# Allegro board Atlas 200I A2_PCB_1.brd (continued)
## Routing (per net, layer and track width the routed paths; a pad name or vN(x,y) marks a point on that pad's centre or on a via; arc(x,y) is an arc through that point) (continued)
TYPEC_CC2: length 12.5
  TOP w0.203: U6.4 v1(102.07,12.01)
  ART03 w0.203: v1(102.07,12.01) 102.18,11.9 102.18,10.08 101.61,9.51 101.61,7.9 103.16,6.34 106.53,6.34 106.92,5.96 106.92,5.35 J4.17
UART0_RX: length 52.3
  TOP w0.203: R253.1 124.92,32.64 125.12,32.44 v1(125.37,32.44) ; R704.2 94.11,46.1 v1(94.44,46.43) 94.25,46.62 J16.14
  ART03 w0.203: v1(125.37,32.44) 125.98,33.05 125.98,35.56 126.88,36.46 126.88,43.51 125.11,45.28 115.85,45.28 114.36,43.78 113.56,43.78 112.59,44.75 110.38,44.75 109.51,43.89 106.03,43.89 105.57,43.43 100.94,43.43 97.94,46.43 v1(94.44,46.43)
UART0_RX_R: length 102.1
  TOP w0.203: v1(121.54,105.79) 121.92,105.79 122.17,105.54 R113.1 ; v1(128.27,36.96) 127.29,36.96 126.5,37.75 U30.3 ; v1(122.57,70.1) 123.12,70.1 R433.1
  ART03 w0.203: v1(122.57,70.1) 119.57,70.1 118.16,68.69 118.16,67.88 114.34,64.06 113.96,64.06 113.69,64.33 113.69,64.71 111.43,66.97 111.43,68.36 111.91,68.84 111.91,77.73 110.74,78.9 110.74,87.44 113.72,90.41 113.72,96.43 120.21,102.92 120.48,102.92 121.54,103.98 v1(121.54,105.79)
  ART04 w0.203: v1(128.27,36.96) 128.98,37.67 128.98,38.93 129.42,39.36 129.42,49.12 124.56,53.97 124.56,69.19 123.75,70 122.66,70 v1(122.57,70.1)
UART0_TX: length 54.4
  TOP w0.203: v1(125.37,31.42) 125.86,31.91 125.86,33.17 R252.1 ; J16.16 93.75,47.55 v1(93.07,46.87) 93.09,46.85 R703.2
  ART03 w0.203: v1(93.07,46.87) 93.97,45.97 97.71,45.97 100.66,43.03 105.74,43.03 106.2,43.48 112.48,43.48 112.98,42.99 117.11,42.99 118.12,44 125.58,44 126.47,43.11 126.47,41.31 125.53,40.36 125.53,33.45 124.84,32.77 124.84,31.94 v1(125.37,31.42)
UART0_TX_R: length 36.3
  TOP w0.203: v1(128.27,37.72) 127.81,37.72 127.69,37.59 127.3,37.59 127.15,37.75 U30.2 ; R51.1 R36.1 123.14,67.06 v1(123.07,67.06)
  ART04 w0.203: v1(128.27,37.72) 127.97,38.02 127.97,40.91 128.92,41.87 128.92,48.9 124.08,53.75 124.08,66.05 v1(123.07,67.06)
UART2_CTX: length 71.6
  TOP w0.203: J16.143 62,59.03 62.89,59.92 62.89,67.15 69.27,73.53 78.37,73.53 80.2,71.7 82.06,71.7 82.8,72.44 v1(82.8,72.64) ; R7.1 v1(115.31,68.23)
  ART04 w0.203: v1(115.31,68.23) 114.43,69.11 109.63,69.11 108.33,70.41 102.11,70.41 101.53,70.99 97.7,70.99 95.91,69.2 92.41,69.2 92.23,69.03 91.85,69.03 91.72,69.15 88.61,69.15 88.09,69.67 86.77,69.67 84.98,71.47 83.98,71.47 v1(82.8,72.64)
UART2_CTX_R: length 5.5
  TOP w0.203: R21.2 113.37,75.31 114.35,76.29 U33.11
UART2_RTX: length 73.7
  TOP w0.203: J16.145 61.5,59.39 62.26,60.14 62.26,67.09 69.1,73.94 78.54,73.94 80.37,72.1 81.89,72.1 82.25,72.45 82.25,72.75 82.77,73.27 83.06,73.27 v1(83.69,72.64) ; R19.1 v1(116.42,68.23)
  ART04 w0.203: v1(116.42,68.23) 115.13,69.52 109.79,69.52 108.5,70.82 102.28,70.82 101.7,71.4 97.13,71.4 95.99,72.54 90.5,72.54 90.3,72.34 90.3,71.75 89.66,71.12 85.9,71.12 85.14,71.88 84.46,71.88 v1(83.69,72.64)
UART2_RTX_R: length 6.7
  TOP w0.203: R29.1 111.07,74.3 111.42,74.65 113.54,74.65 115,76.1 U33.10
UART3_CTX: length 166.4
  TOP w0.203: R50.1 R46.2 ; v1(92.15,50.65) 92.25,50.54 J16.22
  TOP w0.381: R50.1 v1(5.28,106.07)
  ART03 w0.203: v1(5.28,106.07) 5.99,105.36 14.16,105.36 16.24,103.28 20.92,103.28 21.28,103.63 26.67,103.63 29.37,100.93 44.81,100.93 48.54,97.19 53.13,97.19 55.05,95.28 60.48,95.28 v1(60.93,95.73) ; v1(103.89,87.33) 103.89,87.08 103.43,86.63 103.43,86.33 100.3,83.21 100.3,76.49 99.29,75.47 99.29,70.46 98.55,69.73 98.55,67.68 97.28,66.41 97.28,65.2 95.97,63.89 95.97,62.2 92.96,59.19 91.83,59.19 90.64,57.99 90.64,53.64 91.49,52.79 91.49,51.3 v1(92.15,50.65)
  BOTTOM w0.203: v1(103.89,87.33) 104.62,88.05 104.62,89.49 102.39,91.72 101,91.72 96.75,95.97 96.75,96.51 96.48,96.77 96.1,96.77 94.11,98.77 94.11,101.18 89.51,105.78 85.01,105.78 84.72,105.49 84.06,105.49 82.66,104.09 80.99,104.09 77.74,100.84 66.04,100.84 v1(60.93,95.73)
UART3_RTX: length 168.3
  TOP w0.203: v1(92.15,51.92) 92.15,51.29 91.69,50.84 91.69,50.46 91.75,50.4 J16.24 ; R69.2 R67.1 6.91,105.92 v1(7.06,106.07)
  ART03 w0.203: v1(103.89,86.44) 103.89,86.22 100.71,83.04 100.71,76.32 100.43,76.04 100.43,71.03 98.96,69.56 98.96,67.51 98.17,66.72 98.17,63.47 93.32,58.62 91.83,58.62 91.04,57.83 91.04,53.81 92.15,52.71 v1(92.15,51.92) ; v1(58.9,95.73) 55.17,95.73 53.3,97.6 48.71,97.6 44.98,101.33 29.54,101.33 26.28,104.6 21.67,104.6 20.75,103.68 18.23,103.68 15.38,106.53 7.52,106.53 v1(7.06,106.07)
  BOTTOM w0.203: v1(58.9,95.73) 64.55,101.38 76.75,101.38 80.7,105.33 83.33,105.33 83.89,105.89 84.47,105.89 85.33,106.76 89.37,106.76 93.03,103.1 93.58,103.1 94.51,102.16 94.51,98.93 96.27,97.18 96.65,97.18 97.16,96.68 97.16,96.14 101.17,92.13 103.03,92.13 105.71,89.45 105.71,87.81 104.34,86.44 v1(103.89,86.44)
UART3_RX: length 172.8
  TOP w0.203: v1(1.63,106.05) R49.1 R47.2 ; J16.26 91.25,50.92 90.88,51.29 v1(90.88,51.92)
  ART03 w0.203: v1(60.93,94.46) 60.48,94.01 58.65,94.01 58.27,94.39 54.79,94.39 52.89,96.29 48.3,96.29 44.47,100.12 29.04,100.12 26.33,102.82 21.61,102.82 21.26,102.46 10.73,102.46 8.79,104.41 3.26,104.41 v1(1.63,106.05) ; v1(103.89,88.29) 103.15,87.56 103.15,87.09 102.48,86.42 102.48,85.96 98.4,81.88 98.4,76.66 97.02,75.28 97.02,75 98.12,73.89 98.12,67.82 96.88,66.58 96.88,65.37 95.56,64.06 95.56,62.37 92.95,59.75 91.47,59.75 89.54,57.83 89.54,54.35 90.23,53.66 90.23,53.48 90.88,52.83 v1(90.88,51.92)
  BOTTOM w0.203: v1(60.93,94.46) 66.9,100.43 77.9,100.43 81.16,103.68 82.83,103.68 84.22,105.08 85.04,105.08 85.33,105.37 89.01,105.37 93,101.38 93,99.81 93.4,99.41 93.4,96.15 94.05,95.5 96.53,95.5 100.72,91.31 102.22,91.31 104.21,89.32 104.21,88.61 v1(103.89,88.29)
UART3_TX: length 170.7
  TOP w0.203: v1(90.32,51.06) 90.75,50.63 J16.28 ; R68.2 R66.1 v1(3.3,106.05)
  ART03 w0.203: v1(90.32,51.06) 90.32,52.81 89.82,53.31 89.82,53.49 89.14,54.18 89.14,57.99 91.32,60.18 92.8,60.18 95.16,62.53 95.16,64.22 96.47,65.54 96.47,66.74 97.72,67.99 97.72,73.55 96.4,74.86 96.4,75.36 97.99,76.95 97.99,82.05 102.07,86.13 102.07,86.59 102.75,87.26 102.75,87.91 103.63,88.8 v1(103.63,89.26) ; v1(3.3,106.05) 4.39,104.95 13.99,104.95 16.07,102.87 21.09,102.87 21.45,103.23 26.5,103.23 29.2,100.52 44.64,100.52 48.46,96.7 53.05,96.7 54.96,94.79 58.57,94.79 v1(58.9,94.46)
  BOTTOM w0.203: v1(58.9,94.46) 59.36,94.01 61.12,94.01 66.99,99.87 78.2,99.87 81.51,103.17 82.89,103.17 84.39,104.67 85.21,104.67 85.49,104.96 88.84,104.96 92.59,101.22 92.59,99.64 92.99,99.24 92.99,95.11 93.86,94.23 97.22,94.23 100.55,90.91 101.98,90.91 v1(103.63,89.26)
UHT_ALARM: length 59.9
  TOP w0.203: v1(96.04,51.26) 96.27,51.49 97.24,51.49 98.07,52.31 98.07,52.62 99.25,53.8 100.03,53.8 100.76,54.53 v1(101.22,54.53) ; R54.1 92.55,14.13 92.34,13.92 92.34,12.59 92.49,12.44 v1(92.49,11.98)
  TOP w0.254: J16.303 v1(102.5,57.64)
  ART03 w0.203: v1(92.49,11.98) 93.2,11.98 95.83,14.61 95.83,19.34 93.88,21.3 93.88,31.14 94.61,31.88 v1(95.25,31.88)
  ART04 w0.203: v1(95.25,31.88) 95.3,31.88 99.01,35.59 99.01,36.58 98.73,36.86 98.73,44.12 96.85,46 96.85,49.91 96.04,50.73 v1(96.04,51.26)
  BOTTOM w0.203: v1(102.5,57.64) 102.5,55.81 v1(101.22,54.53)
UPDATE_MODE: length 104.1
  TOP w0.203: J16.139 63,58.45 67.29,62.74 80.7,62.74 85.6,67.64 98.6,67.64 100.69,69.72 v1(100.79,69.72) ; v1(126.38,31.42) 126.67,31.42 127.07,31.82 R461.1
  ART04 w0.203: v1(126.38,31.42) 128.75,33.79 128.75,35.81 127.56,37.01 127.56,41.14 128.3,41.87 128.3,48.71 125.01,52 123.31,52 122.43,52.89 122.43,57.44 120.43,59.44 117.26,59.44 115.93,60.77 115.93,61.09 107.82,69.19 101.32,69.19 v1(100.79,69.72)
UPDATE_MODE_R: length 10.6
  TOP w0.203: R461.2 127.88,32.04 128.13,31.79 130.12,31.79 130.33,32 R462.1 C285.2 131.49,32.01 132.03,31.47 S1.2 S1.1
USB0_5V0: length 9
  TOP w0.254: D2.1 57.79,25.02 v1(58.04,25.27)
  BOTTOM w0.254: v1(58.04,25.27) 56.71,25.27 55.64,24.2 55.64,22.79 54.03,21.18 52.78,21.18
  vias: v1(45.06,28.98) v1(50.08,10.97) v1(50.08,10.21) v1(50.08,9.45) v1(50.08,8.69) v1(50.08,7.92) v1(50.08,7.16)
USB1_5V0: length 9.8
  TOP w0.254: v1(55.75,22.1) 56.65,22.99 D2.2
  BOTTOM w0.254: v1(50.16,17.09) 51.84,17.09 53.89,19.15 53.89,20.24 v1(55.75,22.1)
  vias: v1(49.66,17.09) v1(49.66,16.59) v1(50.16,16.59)
USB2_1_CONN_DN: length 21.1
  TOP w0.188: U31.1 47.91,26.69 47.67,26.93 47.67,27.19 47.86,27.38 48.03,27.38 48.13,27.28 48.13,27.13 48.24,27.03 48.51,27.03 48.56,27.08 48.56,27.25 48.69,27.38 48.99,27.38 49.18,27.19 v1(49.18,26.63) 49.45,26.37 T5.3 50.6,26.37 R260.2
  BOTTOM w0.188: v1(49.18,26.63) 48.91,26.36 45.95,26.36 41.73,22.15 41.73,20.88 41.37,20.52 41.13,20.52 40.84,20.4 40.58,20.14 39.55,20.14 38.95,19.54 J5.2
USB2_1_CONN_DP: length 21.4
  TOP w0.188: R261.2 50.6,25.55 T5.2 49.34,25.55 v1(49.18,25.71) 48.74,25.53 48.53,25.32 48.41,25.27 46.47,25.27 46.01,25.72 U31.3
  BOTTOM w0.188: v1(49.18,25.71) 49.18,25.75 48.95,25.98 47.77,25.98 47.58,25.79 47.58,25.74 47.39,25.55 47.01,25.55 46.83,25.74 46.83,25.79 46.64,25.98 46.1,25.98 44.94,24.82 44.94,24.55 45.13,24.36 45.13,24.1 44.86,23.83 44.6,23.83 44.41,24.02 44.14,24.02 43.87,23.75 43.87,23.49 44.06,23.3 44.06,23.03 43.8,22.77 43.53,22.77 43.34,22.95 43.08,22.95 42.11,21.99 42.11,20.73 41.53,20.14 41.21,20.14 41.06,20.08 40.83,19.85 40.83,17.93 40.95,17.81 J5.3
USB2_1_DN: length 82.8
  TOP w0.188: T21.1 103.71,15.65 v1(103.77,15.71) ; J16.123 67,55.08 66.94,55.02 66.94,52.9 68.25,51.59 69.28,51.59 69.63,51.94 70.03,51.94 70.38,51.59 70.78,51.59 71.14,51.94 71.53,51.94 71.89,51.59 72.28,51.59 72.41,51.71 73.27,51.71 73.39,51.59 75.02,51.59 v1(75.25,51.82)
  ART04 w0.173: v1(75.25,51.82) 74.98,51.55 74.67,51.55 74.27,51.15 74.27,42.82 75.03,42.06 75.03,40.77 81.61,34.19 81.61,25.76 78.38,22.53 78.38,18.8 79.25,17.93 79.25,15.51 80.87,13.89 85.24,13.89 85.85,13.28 102.67,13.28 103.5,14.12 103.5,15.45 v1(103.77,15.71)
USB2_1_DP: length 82.8
  TOP w0.188: T21.4 102.9,15.65 v1(102.84,15.71) ; J16.125 66.5,55.08 66.56,55.02 66.56,52.74 68.09,51.21 74.94,51.21 v1(75.25,50.89)
  ART04 w0.173: v1(75.25,50.89) 74.98,51.17 74.82,51.17 74.65,50.99 74.65,42.98 75.41,42.22 75.41,40.92 75.96,40.38 76.36,40.38 76.65,40.09 76.65,39.69 76.84,39.5 77.09,39.5 77.1,39.52 77.35,39.52 77.59,39.27 77.59,39.03 77.57,39.01 77.57,38.76 77.82,38.52 78.06,38.52 78.08,38.54 78.33,38.54 78.57,38.29 78.57,38.05 78.55,38.03 78.55,37.79 78.8,37.54 79.04,37.54 79.06,37.56 79.3,37.56 79.55,37.32 79.55,37.07 79.53,37.05 79.53,36.81 79.77,36.56 80.02,36.56 80.04,36.58 80.28,36.58 80.53,36.34 80.53,36.1 80.51,36.08 80.51,35.83 80.75,35.59 80.99,35.59 81.01,35.61 81.26,35.61 81.5,35.36 81.5,35.12 81.48,35.1 81.48,34.85 81.99,34.35 81.99,25.6 78.77,22.37 78.77,18.95 79.63,18.09 79.63,15.67 81.03,14.27 85.4,14.27 86.01,13.67 102.51,13.67 103.12,14.27 103.12,15.43 v1(102.84,15.71)
USB2_2_CONN_DN: length 23.2
  TOP w0.188: U31.6 47.91,24.09 47.67,24.34 47.67,24.69 47.86,24.87 48.15,24.87 48.62,24.41 48.62,23.96 48.8,23.77 48.99,23.77 49.18,23.96 49.18,24.27 49.37,24.46 v1(49.39,24.46) 49.51,24.33 T8.3 50.6,24.33 R266.2
  BOTTOM w0.102: 39.55,16.89 39.62,16.97 40.58,16.97 40.83,16.84 41.09,16.89 41.35,17.06 41.65,17.18 41.9,17.21 42.61,17.07 42.9,16.94 43.27,16.94 43.58,17.01 43.78,17.07 44.1,17.2 44.87,17.83 45.62,18.14 45.99,18.52
  BOTTOM w0.188: J5.11 38.95,16.29 39.55,16.89 ; v1(49.39,24.46) 49.39,24.42 49.15,24.18 47.93,24.18 47.14,23.39 47.14,20.51 46.79,20.16 46.79,19.32 45.99,18.52
USB2_2_CONN_DP: length 23.3
  TOP w0.188: R267.2 50.6,23.52 T8.2 50.18,23.53 v1(49.39,23.53) 48.8,22.95 48.35,22.76 46.41,22.76 46.01,23.16 U31.4
  BOTTOM w0.102: 40.97,16.29 40.97,16.44 41.24,16.71 41.46,16.86 41.7,16.96 41.89,16.98 42.54,16.85 42.86,16.72 43.29,16.72 43.64,16.78 43.86,16.85 44.22,17 44.99,17.63 45.66,17.91 45.79,17.91 45.81,17.9
  BOTTOM w0.188: 40.97,16.29 40.95,16.27 J5.12 ; v1(49.39,23.53) 49.39,23.57 49.15,23.8 48.09,23.8 47.52,23.24 47.52,22.99 47.71,22.8 47.88,22.8 48.07,22.61 48.07,22.23 47.88,22.05 47.71,22.05 47.52,21.86 47.52,21.48 47.71,21.29 47.85,21.29 48.04,21.11 48.04,20.73 47.85,20.54 47.71,20.54 47.18,20.01 47.18,19.16 46.81,18.79 46.81,18.45 46.98,18.29 46.98,17.96 46.72,17.7 46.44,17.7 46.25,17.9 45.81,17.9
USB2_2_DN: length 73.9
  TOP w0.188: v1(25.41,75.17) 25.15,75.43 25.15,75.99 25.53,76.37 25.53,79.07 R424.1 ; v1(68.96,45.09) 68.68,45.37 68.68,47.28 68.75,47.34 J16.116
  ART04 w0.173: v1(68.96,45.09) 68.69,45.36 68.69,45.8 68.07,47.3 68.07,51.44 68.76,53.1 68.76,56.85 66.95,58.65 66.95,61.85 54.99,73.81 arc(54.79,73.94) 54.56,73.99 25.79,73.99 25.13,74.65 25.13,74.9 v1(25.41,75.17)
USB2_2_DP: length 75.8
  TOP w0.188: v1(24.48,75.17) 24.77,75.45 24.77,76.15 25.15,76.53 25.15,79.04 R416.1 ; J16.118 68.25,47.37 68.3,47.32 68.3,45.35 v1(68.04,45.09)
  ART04 w0.173: v1(24.48,75.17) 24.75,74.9 24.75,74.49 25.64,73.61 27.89,73.61 28.17,73.33 28.58,73.33 28.86,73.61 29.27,73.61 29.55,73.33 29.96,73.33 30.24,73.61 30.65,73.61 30.93,73.33 31.34,73.33 31.62,73.61 32.03,73.61 32.31,73.33 32.72,73.33 33,73.61 33.41,73.61 33.69,73.33 34.1,73.33 34.38,73.61 34.8,73.61 35.07,73.33 35.49,73.33 35.77,73.61 36.18,73.61 36.46,73.33 36.87,73.33 37.15,73.61 37.56,73.61 37.84,73.33 38.25,73.33 38.53,73.61 54.56,73.61 arc(54.65,73.59) 54.72,73.54 66.57,61.69 66.57,58.49 68.38,56.69 68.38,53.18 67.69,51.52 67.69,47.22 68.31,45.73 68.31,45.36 v1(68.04,45.09)
USB2_3_DN: length 47.8
  TOP w0.188: R475.2 91.33,87.2 v1(91.8,86.73) ; v1(68.71,59.8) 68.44,59.53 68.44,57.01 68.5,56.95 J16.117
  BOTTOM w0.188: v1(68.71,59.8) 68.44,60.08 68.44,60.91 71.3,63.77 71.3,68.17 74.8,71.68 74.8,75.38 75.64,76.22 75.64,77.01 80.73,82.09 84.13,82.09 86,83.96 86,85.42 87.09,86.51 87.6,86.51 87.88,86.79 87.88,87.3 89.24,88.65 89.78,88.65 91.2,87.24 91.42,87.24 91.8,86.86 v1(91.8,86.73)
USB2_3_DP: length 47.8
  TOP w0.188: R468.2 92.21,87.2 v1(91.8,87.62) ; v1(67.79,59.8) 68.06,59.53 68.06,57.03 68,56.98 J16.119
  BOTTOM w0.188: v1(67.79,59.8) 68.06,60.08 68.06,61.07 70.92,63.92 70.92,68.33 74.42,71.84 74.42,75.54 75.26,76.38 75.26,77.16 80.57,82.47 83.97,82.47 85.62,84.12 85.62,85.57 89.08,89.03 89.94,89.03 91.36,87.62 v1(91.8,87.62)
USB2_3_HUB0_DN: length 21.2
  TOP w0.188: v1(92.03,89.68) 92.03,89.52 91.12,88.61 R474.1 ; U38.54 82.99,95.77 82.34,95.12 81.97,95.12 v1(81.69,94.84)
  ART03 w0.173: v1(81.69,94.84) 81.94,95.09 82.44,95.09 82.6,94.94 82.6,94.87 82.75,94.72 82.96,94.72 83.11,94.87 83.11,94.94 83.27,95.09 83.92,95.09 84.42,94.59 87.81,94.59 88.4,95.17 91.23,95.17 91.57,94.83 91.57,92.53 91.74,92.35 91.74,90.72 92.28,90.19 92.28,89.93 v1(92.03,89.68)
USB2_3_HUB0_DP: length 21.2
  TOP w0.188: U38.53 83.89,96.15 82.83,96.15 82.19,95.51 81.9,95.51 v1(81.69,95.72) ; v1(92.92,89.68) 92.46,89.23 R468.1
  ART03 w0.173: v1(92.92,89.68) 92.66,89.94 92.66,90.35 92.13,90.88 92.13,92.51 91.95,92.69 91.95,94.99 91.38,95.55 88.24,95.55 87.66,94.97 84.58,94.97 84.08,95.47 81.94,95.47 v1(81.69,95.72)
USB2_3_HUB1_DN: length 1.9
  TOP w0.188: R475.1 91.56,85.32 91.75,85.14 U36.57
USB2_3_HUB1_DP: length 1.9
  TOP w0.188: U36.56 92.15,85.57 92.46,85.88 R473.1
USB3_1_CONN_RX_N: length 9.2
  TOP w0.188: R263.2 40.92,25.82 40.97,25.77 T6.3 40.97,25.34 40.96,25.33 40.96,24.79 41.65,24.11 D9.10 D9.1 41.65,22.42 41.23,22.01 v1(41.01,22.01)
  ART03 w0.173: J5.5 43.95,19.37 43.3,20.02 43.3,20.26 43.39,20.35 43.39,20.59 43.15,20.84 42.9,20.84 42.82,20.75 42.57,20.75 41.58,21.74 41.28,21.74 v1(41.01,22.01)
USB3_1_CONN_RX_P: length 9.2
  TOP w0.188: v1(41.01,21.08) 41.15,21.08 42.14,22.08 D9.2 D9.9 42.14,24.15 41.78,24.51 T6.2 41.78,25.77 41.83,25.82 R262.2
  ART03 w0.173: J5.6 41.95,19.28 42.36,19.28 42.78,19.7 42.78,20 41.43,21.36 41.28,21.36 v1(41.01,21.08)
USB3_1_CONN_TX_N: length 7.7
  TOP w0.188: v1(36.3,22.07) 36.93,22.71 D10.1 D10.10 36.93,24.11 36.59,24.45 36.27,25.22 T7.3 36.27,25.8 R264.2
  ART03 w0.173: v1(36.3,22.07) 37.31,21.06 37.31,19.92 J5.8
USB3_1_CONN_TX_P: length 8.5
  TOP w0.188: R265.2 37.08,25.8 T7.2 37.01,25.32 37.01,24.61 37.43,24.19 D10.9 D10.2 37.43,22.64 37.05,22.06 v1(36.3,21.15)
  ART03 w0.173: v1(36.3,21.15) 36.49,21.34 36.93,20.9 36.93,19.81 36.4,19.28 J5.9
USB3_1_RX_N: length 69.3
  TOP w0.188: v1(106.26,18.21) 106.54,17.94 106.54,16.73 106.99,16.28 106.99,16.01 106.93,15.96 U5.8 ; J16.92 74.75,47.36 74.69,47.3 74.69,46.49 74.88,46.3 75.03,46.3 v1(75.25,46.52)
  ART04 w0.173: v1(75.25,46.52) 75.52,46.25 76.1,46.25 76.49,45.86 76.49,43.58 76.67,43.41 76.69,43.41 76.86,43.24 76.86,42.89 76.69,42.72 76.67,42.72 76.49,42.55 76.49,41.82 83.2,35.11 83.2,23.05 80.59,20.44 80.59,17.61 82.56,15.65 98.26,15.65 98.44,15.82 98.44,16.14 98.73,16.44 99.11,16.44 99.39,16.71 100.07,16.71 100.29,16.94 100.76,16.94 100.99,16.71 101.45,16.71 101.68,16.94 102.14,16.94 102.37,16.71 102.83,16.71 103.06,16.94 103.52,16.94 103.75,16.71 104.21,16.71 104.44,16.94 104.9,16.94 105.13,16.71 105.63,16.71 106.54,17.62 106.54,17.94 v1(106.26,18.21)
USB3_1_RX_P: length 69.4
  TOP w0.188: U5.7 107.43,15.96 107.37,16.01 107.37,16.44 106.92,16.89 106.92,17.94 v1(107.19,18.21) ; v1(75.25,45.6) 74.92,45.92 74.72,45.92 74.31,46.33 74.31,47.3 74.25,47.36 J16.94
  ART04 w0.173: v1(75.25,45.6) 75.52,45.87 75.94,45.87 76.11,45.7 76.11,41.66 82.82,34.95 82.82,23.21 80.21,20.6 80.21,17.45 82.4,15.27 98.42,15.27 98.82,15.66 98.88,15.66 99.55,16.33 105.79,16.33 106.92,17.46 106.92,17.94 v1(107.19,18.21)
USB3_1_TX_N: length 81.1
  TOP w0.188: v1(109.01,18.21) 109.02,18.2 C310.2 ; v1(75,58.4) 75,58.48 74.84,58.65 74.64,58.65 74.45,58.46 74.45,57.03 74.5,56.98 J16.93
  ART04 w0.173: v1(109.01,18.21) 109.3,18.5 109.3,18.75 108.19,19.86 106.93,19.86 106.7,19.63 106.24,19.63 106.01,19.86 105.55,19.86 105.32,19.63 104.86,19.63 104.63,19.86 104.17,19.86 103.94,19.63 103.48,19.63 103.25,19.86 102.79,19.86 102.56,19.63 102.1,19.63 101.87,19.86 100.75,19.86 100.04,19.57 99.67,19.2 99.67,18.88 99.35,18.55 99.02,18.55 98.7,18.22 98.7,17.9 98.37,17.57 98.05,17.57 96.83,16.36 83.58,16.36 81.95,18 81.95,20.03 84.15,22.24 84.15,35.45 79.5,40.1 79.5,42.59 77.22,44.88 77.22,51.73 75.56,53.39 75.56,58.53 75.39,58.7 75.25,58.7 75,58.45 v1(75,58.4)
USB3_1_TX_P: length 81.1
  TOP w0.188: J16.95 74,56.95 74.06,57.01 74.06,57.03 74.07,57.03 74.07,58.62 74.48,59.03 74.81,59.03 75,59.22 v1(75,59.33) ; C308.2 109.93,18.21 v1(109.93,18.21)
  ART04 w0.173: v1(109.93,18.21) 109.93,18.25 109.68,18.5 109.68,18.91 108.35,20.24 100.67,20.24 99.83,19.89 96.67,16.74 83.74,16.74 82.33,18.15 82.33,19.87 84.53,22.08 84.53,35.61 79.88,40.26 79.88,42.75 77.6,45.03 77.6,51.89 75.95,53.54 75.95,58.68 75.55,59.08 75.25,59.08 v1(75,59.33)
USB3_2_CONN_RX_N: length 14.7
  TOP w0.188: v1(43.4,21.5) 43.15,21.75 D9.4 D9.7 43.15,24.3 43.43,24.59 T9.3 43.43,25.77 43.38,25.82 R269.2
  ART04 w0.173: v1(43.4,21.5) 43.67,21.23 43.67,20.82 43.55,20.7 43.42,20.7 43.29,20.57 43.29,20.33 43.46,20.16 44.33,20.16 45.11,19.39 45.11,18.45 44.93,18.27 44.74,18.27 44.57,18.1 44.57,17.75 44.74,17.58 44.93,17.58 45.11,17.41 45.11,17.14 44.85,16.89 43.31,16.89 43.14,16.72 43.14,16.25 43.31,16.08 J5.14
USB3_2_CONN_RX_P: length 14.7
  TOP w0.188: R268.2 44.3,25.82 44.25,25.77 T9.2 44.25,25.23 43.65,23.78 D9.6 D9.5 43.65,22.17 v1(44.32,21.5)
  ART04 w0.173: J5.15 42.31,15.78 43.3,15.43 43.78,15.3 44.13,15.3 44.38,15.35 44.68,15.48 44.95,15.74 45.49,17.05 45.49,19.54 44.05,20.98 44.05,21.23 v1(44.32,21.5)
USB3_2_CONN_TX_N: length 17.3
  TOP w0.188: v1(38.81,21.5) 38.81,21.66 38.46,22.01 38.46,22.94 D10.4 D10.7 38.43,24.56 38.58,24.71 T10.3 38.58,25.77 38.53,25.82 R270.2
  ART04 w0.173: J5.17 37.86,15.99 36.35,15.36 35.94,15.28 35.52,15.28 35.06,15.59 34.49,16.96 34.49,19.71 35.33,20.55 38.25,20.55 38.81,21.11 v1(38.81,21.5)
USB3_2_CONN_TX_P: length 17.2
  TOP w0.188: R271.2 39.44,25.82 39.39,25.77 T10.2 39.39,25.17 39.2,24.71 38.93,24.44 D10.6 D10.5 38.9,22.94 38.9,22.18 39.59,21.5 v1(39.74,21.5)
  ART04 w0.173: v1(39.74,21.5) 39.23,20.99 39.23,20.74 38.87,20.38 38.61,20.38 38.41,20.17 37.38,20.17 37.1,19.89 36.62,19.89 36.34,20.17 35.49,20.17 34.87,19.55 34.87,17.09 35.05,16.92 36.76,16.92 36.93,16.74 36.93,16.28 36.76,16.11 35.98,16.11 J5.18
USB3_3_RX_HUB0_N: length 23.7
  TOP w0.188: U38.47 83.07,98.57 82.78,98.86 80.98,98.86 v1(80.77,99.06) ; v1(89.96,89.51) 89.74,89.29 89.74,88.9 90.09,88.55 C108.2
  ART03 w0.173: v1(89.96,89.51) 89.66,89.8 89.66,90.11 89.27,90.51 88.58,90.51 88.29,90.8 88.29,91.38 87.77,91.9 82.47,91.9 80.39,93.98 80.39,96.08 80.77,96.45 81.01,96.45 81.84,97.28 81.84,98.47 81.44,98.87 80.96,98.87 v1(80.77,99.06)
USB3_3_RX_HUB0_P: length 23.8
  TOP w0.188: C107.2 88.75,88.38 89.19,88.83 89.19,89.39 v1(89.07,89.51) ; U38.48 82.93,98.17 82.63,98.48 80.95,98.48 v1(80.77,98.3)
  ART03 w0.173: v1(89.07,89.51) 89.1,89.54 89.11,89.54 89.28,89.71 89.28,89.95 89.11,90.13 88.42,90.13 87.91,90.64 87.91,91.22 87.61,91.52 85.48,91.52 85.33,91.36 84.71,91.36 84.56,91.52 84.1,91.52 83.87,91.29 83.41,91.29 83.18,91.52 82.32,91.52 81.75,92.08 81.4,92.08 81.09,92.39 81.09,92.74 80.01,93.82 80.01,94.11 79.81,94.31 79.81,94.87 80.01,95.08 80.01,96.24 80.61,96.83 80.85,96.83 81.46,97.44 81.46,98.32 81.29,98.49 80.96,98.49 v1(80.77,98.3)
USB3_3_RX_HUB1_N: length 4.6
  TOP w0.188: C105.2 89.94,86.06 89.94,85.45 90.41,84.98 90.89,84.98 91.06,84.81 91.06,84.58 90.89,84.41 90.54,84.41 90.35,84.22 90.35,83.66 90.59,83.42 U36.59
USB3_3_RX_HUB1_P: length 4.6
  TOP w0.188: C106.2 88.75,85.75 89.2,85.29 89.48,85.29 89.97,84.81 89.97,83.5 90.45,83.02 U36.60
USB3_3_RX_N: length 59.3
  TOP w0.188: J16.104 71.75,47.7 71.69,47.64 71.69,46.84 v1(71.96,46.57) ; C105.1 89.84,87.02 v1(89.42,87.44)
  ART04 w0.173: v1(71.96,46.57) 71.69,46.84 71.69,47.58 73.23,49.12 73.23,50.87 74.37,52.01 74.37,60.12 75.92,61.67 75.92,66.31 76.05,66.44 76.33,66.44 76.45,66.32 v1(76.45,66.17)
  BOTTOM w0.188: v1(89.42,87.44) 89.52,87.44 89.76,87.2 90.25,87.2 91.22,86.23 91.22,78.12 88.11,75.01 84.88,75.01 83.82,75.45 80.6,75.45 78.56,73.41 78.56,67.56 77.44,66.45 76.73,66.45 v1(76.45,66.17)
USB3_3_RX_P: length 59.3
  TOP w0.188: v1(89.42,86.55) 88.95,87.02 C106.1 ; J16.106 71.25,47.72 71.31,47.66 71.31,46.84 v1(71.04,46.57)
  ART04 w0.173: v1(71.04,46.57) 71.31,46.84 71.31,47.74 71.76,48.19 71.76,48.5 72.1,48.83 72.4,48.83 72.85,49.28 72.85,51.03 73.1,51.28 73.1,51.66 73.4,51.96 73.78,51.96 73.99,52.17 73.99,53.32 73.71,53.6 73.71,54.01 73.99,54.29 73.99,60.28 75.54,61.83 75.54,66.47 75.89,66.82 76.32,66.82 76.45,66.95 v1(76.45,67.1)
  BOTTOM w0.188: v1(76.45,67.1) 76.72,66.83 77.29,66.83 78.18,67.72 78.18,73.56 80.44,75.83 83.89,75.83 84.96,75.39 87.95,75.39 90.84,78.28 90.84,86.07 90.09,86.82 89.79,86.82 89.52,86.55 v1(89.42,86.55)
USB3_3_TX_HUB0_N: length 18
  TOP w0.188: v1(84.66,97.6) 84.43,97.37 U38.50 ; C111.2 86.7,84.97 84.76,84.97 v1(84.26,84.46)
  BOTTOM w0.188: v1(84.26,84.46) 84.51,84.71 84.51,84.81 83.55,85.77 83.55,96.92 83.99,97.36 84.41,97.36 v1(84.66,97.6)
USB3_3_TX_HUB0_P: length 18
  TOP w0.188: C110.2 85.86,83.74 v1(85.14,84.46) ; v1(84.66,96.67) 84.36,96.97 U38.51
  BOTTOM w0.188: v1(85.14,84.46) 85.14,84.46 84.89,84.71 84.89,84.97 83.93,85.93 83.93,87.96 84.12,88.15 84.19,88.15 84.38,88.34 84.38,88.71 84.19,88.9 84.12,88.9 83.93,89.09 83.93,89.47 84.12,89.65 84.19,89.65 84.38,89.84 84.38,90.22 84.19,90.4 84.12,90.4 83.93,90.59 83.93,90.97 84.12,91.16 84.19,91.16 84.38,91.34 84.38,91.72 84.19,91.91 84.12,91.91 83.93,92.1 83.93,96.76 84.15,96.98 84.41,96.98 84.66,96.73 v1(84.66,96.67)
USB3_3_TX_HUB1_N: length 4.2
  TOP w0.188: U36.62 90.58,82.22 89.59,83.22 89.59,83.93 89.3,84.61 89.11,84.81 89.11,84.81 C96.2
USB3_3_TX_HUB1_P: length 4.2
  TOP w0.188: C97.2 88.62,83.92 89.02,83.92 89.2,83.73 89.2,83.06 89.75,82.52 89.75,82.01 89.99,81.77 90.4,81.77 90.46,81.82 U36.63
USB3_3_TX_N: length 44.8
  TOP w0.188: C111.1 87.63,84.89 v1(88.1,84.42) ; J16.105 71.5,56.98 71.45,57.03 71.45,58.46 71.64,58.65 71.84,58.65 72,58.48 v1(72,58.4)
  ART04 w0.173: v1(72,58.4) 72.27,58.67 72.68,58.67 73.13,59.13 73.13,60.68 74.47,62.02 74.47,66.26 74.65,66.44 74.83,66.44 74.95,66.32 v1(74.95,66.17)
  BOTTOM w0.188: v1(74.95,66.17) 75.23,66.44 75.54,66.44 75.95,66.85 75.95,68.4 77.17,69.62 77.17,74.57 80.04,77.44 80.64,77.44 81.18,76.91 83.82,76.91 85.1,78.19 88.91,78.19 89.76,79.05 89.76,82.5 89.16,83.11 88.47,83.11 87.83,83.75 87.83,84.15 v1(88.1,84.42)
USB3_3_TX_P: length 44.8
  TOP w0.188: v1(72,59.33) 72,59.22 71.81,59.03 71.48,59.03 71.07,58.62 71.07,57.03 71.06,57.03 71.06,57.01 71,56.95 J16.107 ; v1(87.21,84.42) 87.63,84 C110.1
  ART04 w0.173: v1(72,59.33) 72.27,59.05 72.52,59.05 72.75,59.28 72.75,60.83 74.09,62.18 74.09,66.42 74.49,66.82 74.85,66.82 74.95,66.93 v1(74.95,67.1)
  BOTTOM w0.188: v1(87.21,84.42) 87.45,84.18 87.45,83.59 88.32,82.73 89,82.73 89.38,82.35 89.38,79.2 88.75,78.57 84.94,78.57 83.66,77.29 81.34,77.29 80.8,77.83 79.88,77.83 76.78,74.73 76.78,69.78 75.57,68.56 75.57,67.01 75.38,66.82 75.23,66.82 v1(74.95,67.1)
USB3_3_TYPEA1_HUB0_RX1_N: length 31
  TOP w0.188: v1(95.53,94.86) 95.17,95.22 95.17,95.37 94.76,95.78 93.6,95.78 93.21,96.17 U38.5 ; v1(85.4,79.14) 85.62,78.92 R432.1
  ART03 w0.173: v1(85.4,79.14) 85.73,79.14 86.21,78.66 89.38,78.66 90.5,79.78 90.5,82.02 91.57,83.08 92.29,83.08 97.03,87.83 97.03,90.39 97.72,91.09 97.72,91.09 97.74,91.11 97.74,93.17 96.65,94.26 95.53,94.26 95.35,94.44 95.35,94.69 v1(95.53,94.86)
USB3_3_TYPEA1_HUB0_RX1_P: length 31
  TOP w0.188: v1(85.4,80.03) 85.62,80.26 R430.1 ; v1(94.64,94.86) 94.73,94.95 94.73,95.24 94.56,95.4 93.44,95.4 93.07,95.77 U38.4
  ART03 w0.173: v1(85.4,80.03) 85.4,80.02 86.37,79.04 89.22,79.04 90.12,79.94 90.12,80.7 89.95,80.88 89.65,80.88 89.48,81.05 89.48,81.4 89.65,81.57 89.95,81.57 90.12,81.74 90.12,82.17 91.41,83.46 92.13,83.46 96.65,87.98 96.65,88.27 96.32,88.6 96.32,88.96 96.65,89.29 96.65,90.55 97.34,91.25 97.34,91.25 97.36,91.27 97.36,93.01 96.49,93.88 95.38,93.88 94.92,94.34 94.92,94.58 v1(94.64,94.86)
USB3_3_TYPEA1_HUB0_TX1_N: length 22.8
  TOP w0.188: U38.2 93.12,94.97 93.76,94.34 94.34,94.34 94.93,93.74 94.93,93.5 v1(95.28,93.16) ; C372.1 85.62,81.33 v1(85.4,81.56)
  ART03 w0.173: v1(95.28,93.16) 95.05,92.93 95.05,90.65 94.67,90.27 94.67,87.35 92.46,85.14 91.02,85.14 88.42,82.55 86.33,82.55 85.96,82.18 85.96,82.12 v1(85.4,81.56)
USB3_3_TYPEA1_HUB0_TX1_P: length 22.8
  TOP w0.188: v1(85.4,82.44) 85.62,82.67 C112.1 ; v1(94.39,93.16) 94.55,93.32 94.55,93.59 94.18,93.95 93.6,93.95 92.98,94.57 U38.1
  ART03 w0.173: v1(94.39,93.16) 94.67,92.88 94.67,92.61 94.34,92.28 94.34,91.92 94.67,91.59 94.67,90.81 94.28,90.43 94.28,88.85 93.98,88.54 93.98,88.15 94.28,87.85 94.28,87.51 93.94,87.17 93.73,87.17 93.64,87.25 93.43,87.25 93.28,87.1 93.28,86.89 93.36,86.8 93.36,86.59 92.3,85.53 90.86,85.53 90.57,85.23 90.35,85.23 90.34,85.25 90.12,85.25 89.97,85.09 89.97,84.88 89.98,84.86 89.98,84.65 88.26,82.93 87.68,82.93 87.38,83.24 86.99,83.24 86.69,82.93 85.88,82.93 v1(85.4,82.44)
USB3_3_TYPEA1_HUB1_RX1_N: length 2.7
  TOP w0.188: R431.1 88.82,78.92 89.33,79.42 90.34,79.42 90.34,79.42 U36.69
USB3_3_TYPEA1_HUB1_RX1_P: length 2.7
  TOP w0.188: R429.1 88.86,80.26 89.29,79.82 U36.68
USB3_3_TYPEA1_HUB1_TX1_N: length 3.3
  TOP w0.188: U36.66 90.33,80.62 90.31,80.64 89.73,80.64 89.68,80.59 89.36,80.59 89.15,80.81 89.15,81.12 89.2,81.17 89.2,81.34 89.08,81.46 88.57,81.46 C371.1
USB3_3_TYPEA1_HUB1_TX1_P: length 3.3
  TOP w0.188: C114.1 89.19,82.36 89.31,82.24 89.31,81.86 90.15,81.02 U36.65
USB3_3_TYPEA1_HUB_RX1_N: length 102.5
  TOP w0.188: v1(40.92,28.41) 41.13,28.21 41.13,27.94 40.97,27.78 T6.4 40.97,26.71 R263.1 ; R431.2 87.63,79.12 v1(88.1,79.59)
  ART03 w0.173: v1(88.1,79.59) 88.1,79.6 88.09,79.61 88.03,79.61 87.83,79.8 87.83,80.15 87.44,80.54 86.31,80.54 85.93,80.92 85.09,80.92 83.26,79.1 83.26,77.32 81.48,75.54 78.18,75.54 71.02,68.38 71.02,65.23 70.41,64.62 70.41,64.62 70.05,64.08 69.6,63.62 69.06,63.26 66.25,62.06 64.02,59.83 64.02,47.43 65.58,45.87 65.58,43.27 66.08,42.77 66.08,42.07 67.97,40.18 67.97,37.08 67.27,36.39 67.27,30.35 63.27,26.34 62.75,26.34 61.43,27.66 54.64,27.66 53.76,26.77 51.49,26.77 50.25,28.01 48.16,28.01 45.72,30.45 41.68,30.45 41.2,29.97 41.2,28.69 v1(40.92,28.41)
USB3_3_TYPEA1_HUB_RX1_P: length 102.4
  TOP w0.188: v1(41.85,28.41) 41.63,28.2 41.63,27.93 41.78,27.78 T6.1 41.78,26.71 R262.1 ; v1(87.21,79.59) 87.63,80.01 R429.2
  ART03 w0.173: v1(87.21,79.59) 87.3,79.59 87.45,79.74 87.45,79.99 87.28,80.16 86.16,80.16 85.78,80.54 85.25,80.54 83.64,78.94 83.64,77.17 81.64,75.16 78.33,75.16 71.4,68.22 71.4,65.07 70.71,64.38 70.35,63.84 69.84,63.33 69.24,62.93 66.47,61.74 64.4,59.67 64.4,47.59 65.96,46.02 65.96,43.42 66.46,42.93 66.46,42.23 68.35,40.34 68.35,36.93 67.66,36.23 67.66,30.19 63.42,25.96 62.59,25.96 61.27,27.27 54.8,27.27 53.91,26.39 52.71,26.39 52.48,26.16 52.02,26.16 51.79,26.39 51.33,26.39 50.09,27.63 48.01,27.63 47.57,28.06 47.33,28.06 47.31,28.04 47.06,28.04 46.82,28.29 46.82,28.53 46.84,28.55 46.84,28.8 46.54,29.09 46.19,29.09 45.88,29.41 45.88,29.76 45.56,30.07 44.92,30.07 44.64,29.79 44.23,29.79 43.95,30.07 43.54,30.07 43.26,29.79 42.85,29.79 42.57,30.07 41.84,30.07 41.58,29.81 41.58,28.59 41.76,28.41 v1(41.85,28.41)
USB3_3_TYPEA1_HUB_TX1_N: length 131
  TOP w0.188: R264.1 36.27,26.71 T7.4 36.27,27.78 36.43,27.94 36.43,28.21 v1(36.22,28.41) ; v1(88.1,82) 87.63,81.54 C371.2
  ART04 w0.173: v1(73.45,66.17) 73.18,66.44 73.05,66.44 72.87,66.27 72.87,62.65 71.34,61.12 71.34,52.83 70.28,50.26 70.28,46.9 70.56,46.24 71.79,45 73.41,41.11 73.41,32.64 75.47,27.65 75.47,20.32 76.83,17.03 76.83,15.52 73.96,12.65 65.49,12.65 65.24,12.9 59.91,12.9 58.72,14.1 55.14,14.1 44.7,24.54 39.06,24.54 36.49,27.11 36.49,28.14 v1(36.22,28.41)
  BOTTOM w0.188: v1(88.1,82) 87.81,81.71 87.81,81.1 87.31,80.59 85.12,80.59 84.49,79.97 84.1,79.58 81.38,79.58 80.77,78.97 80.14,78.97 76.05,74.88 76.05,70.08 74.45,68.48 74.45,66.85 74.04,66.44 73.73,66.44 v1(73.45,66.17)
USB3_3_TYPEA1_HUB_TX1_P: length 130.2
  TOP w0.188: R265.1 37.08,26.71 T7.1 37.08,27.78 36.93,27.93 36.93,28.2 v1(37.15,28.41) ; v1(87.21,82) 87.63,82.42 C112.2
  ART04 w0.173: v1(73.45,67.1) 73.18,66.82 72.89,66.82 72.49,66.43 72.49,62.8 70.96,61.28 70.96,52.9 69.9,50.34 69.9,46.83 70.07,46.42 70.23,46.02 71.47,44.79 73.03,41.03 73.03,32.56 75.09,27.57 75.09,20.24 76.45,16.96 76.45,15.68 73.81,13.03 65.65,13.03 65.4,13.28 60.07,13.28 58.88,14.48 55.3,14.48 44.86,24.92 39.22,24.92 38.45,25.69 38.45,25.99 38.23,26.21 37.93,26.21 37.71,26.43 37.71,26.73 37.5,26.94 37.2,26.94 36.87,27.27 36.87,28.14 v1(37.15,28.41)
  BOTTOM w0.188: v1(73.45,67.1) 73.73,66.82 73.88,66.82 74.07,67.01 74.07,68.64 74.51,69.08 74.51,69.4 74.88,69.77 75.2,69.77 75.67,70.24 75.67,75.04 79.98,79.35 80.61,79.35 81.22,79.96 83.95,79.96 84.34,80.35 84.96,80.98 87.15,80.98 87.43,81.25 87.43,81.79 v1(87.21,82)
USB3_3_TYPEA2_HUB0_RX2_N: length 32.8
  TOP w0.188: R451.1 96.39,68.83 v1(96.17,68.61) ; v1(91.2,91.82) 91.06,91.69 90.79,91.69 90.37,92.11 90.37,93.18 90.29,93.26 U38.72
  BOTTOM w0.188: v1(91.2,91.82) 91.45,91.57 91.76,91.57 92.17,91.16 92.17,90.84 92.42,90.58 94.03,90.58 95.38,89.24 95.38,86.67 98.23,83.82 98.23,76.84 97.28,75.9 97.28,72.86 97.47,72.67 97.5,72.67 97.69,72.48 97.69,72.11 97.5,71.92 97.47,71.92 97.28,71.73 97.28,69.92 96.17,68.81 v1(96.17,68.61)
USB3_3_TYPEA2_HUB0_RX2_P: length 32.8
  TOP w0.188: v1(95.28,68.61) 95.06,68.83 R441.1 ; U38.71 89.89,93.12 89.99,93.02 89.99,91.95 90.73,91.21 90.92,91.21 v1(91.2,90.93)
  BOTTOM w0.188: v1(91.2,90.93) 91.45,91.19 91.6,91.19 91.79,91 91.79,90.68 92.27,90.2 93.87,90.2 95,89.08 95,86.51 97.85,83.66 97.85,77 96.9,76.05 96.9,70.08 95.43,68.61 v1(95.28,68.61)
USB3_3_TYPEA2_HUB0_TX2_N: length 32
  TOP w0.188: U38.69 89.09,93.33 89.07,93.31 89.07,92.3 89.29,92.08 v1(89.49,92.08) ; C376.1 93.98,68.83 v1(93.75,68.61)
  BOTTOM w0.188: v1(93.75,68.61) 93.75,68.86 94.44,69.54 94.44,72.01 95.68,73.25 95.68,76.07 93.63,78.13 93.63,81.3 93.14,81.79 93.14,85.4 93.5,85.75 93.5,86.15 93.14,86.5 93.14,86.9 93.5,87.26 93.5,87.65 93.14,88.01 93.14,88.8 92.73,89.21 91.27,89.21 90.85,89.62 90.53,90.42 90.53,91.44 90.11,91.85 89.72,91.85 v1(89.49,92.08)
USB3_3_TYPEA2_HUB0_TX2_P: length 32
  TOP w0.188: C374.1 92.64,68.83 v1(92.87,68.61) ; U38.68 88.69,92.06 89.49,91.26 v1(89.49,91.19)
  BOTTOM w0.188: v1(89.49,91.19) 89.49,91.24 89.72,91.47 89.96,91.47 90.14,91.28 90.14,90.34 90.53,89.41 91.11,88.83 92.57,88.83 92.76,88.64 92.76,81.63 93.25,81.14 93.25,77.97 95.3,75.92 95.3,73.41 94.06,72.17 94.06,69.7 92.97,68.61 v1(92.87,68.61)
USB3_3_TYPEA2_HUB1_RX2_N: length 4.5
  TOP w0.188: U36.12 96.15,73.06 95.89,72.8 95.89,72.53 96.17,72.26 96.17,71.88 R446.1
USB3_3_TYPEA2_HUB1_RX2_P: length 4.5
  TOP w0.188: U36.11 95.75,75.32 95.77,75.3 95.77,73.21 95.51,72.96 95.51,72.5 95.27,72.26 95.27,71.87 R434.1
USB3_3_TYPEA2_HUB1_TX2_N: length 5.2
  TOP w0.188: U36.9 94.95,75.38 95.08,75.25 95.08,74.53 94.72,74.17 94.72,73.08 94.6,72.96 94.6,72.7 94.63,72.67 94.63,72.4 94.45,72.21 93.89,72.21 93.81,72.13 93.81,71.83 C375.1
USB3_3_TYPEA2_HUB1_TX2_P: length 5.2
  TOP w0.188: C373.1 92.63,71.68 92.89,72.29 93.12,72.52 93.81,72.81 94.34,73.33 94.34,74.33 94.7,74.69 94.7,75.1 94.55,75.24 U36.8
USB3_3_TYPEA2_HUB_RX2_N: length 106.9
  TOP w0.188: R451.2 96.14,70.84 v1(95.72,70.42) ; R269.1 43.43,26.71 T9.4 43.43,27.78 43.59,27.94 43.59,28.21 v1(43.38,28.41)
  ART03 w0.173: v1(43.38,28.41) 43.38,28.36 43.56,28.19 43.56,27.88 43.96,27.48 44.5,27.48 44.73,27.39 44.83,27.29 45.4,25.92 45.83,25.48 45.83,25.24 45.8,25.2 45.8,24.96 46.04,24.72 46.29,24.72 46.32,24.75 46.57,24.75 46.81,24.51 46.81,24.26 46.78,24.23 46.78,23.98 47.02,23.74 47.27,23.74 47.3,23.77 47.54,23.77 48.09,23.23 48.09,22.41 48.58,21.92 49.94,21.92 50.34,22.32 50.34,22.78 51.01,23.45 55.31,23.45 55.31,23.45 55.32,23.45 55.83,22.94 58.98,22.94 59.35,23.31 62.17,23.31 62.64,23.77 67.46,23.77 69.02,25.33 69.02,25.89 72.16,29.03 72.16,39.66 71.81,40.01 71.81,44.93 70.21,46.53 70.21,53.81 69.81,54.21 69.81,58.12 70.08,58.39 70.08,59.18 74.4,63.5 74.4,68.07 76.5,70.18 77.62,70.18 78.74,71.3 87.17,71.3 88.57,72.69 94.63,72.69 94.81,72.52 94.81,71.12 95.21,70.71 95.43,70.71 v1(95.72,70.42)
USB3_3_TYPEA2_HUB_RX2_P: length 106.9
  TOP w0.188: v1(44.31,28.41) 44.09,28.2 44.09,27.93 44.25,27.78 T9.1 44.25,26.71 R268.1 ; v1(95.72,71.31) 95.25,70.84 R434.2
  ART03 w0.173: v1(95.72,71.31) 95.51,71.09 95.37,71.09 95.19,71.28 95.19,72.68 94.79,73.08 88.41,73.08 87.01,71.68 78.58,71.68 77.46,70.56 76.35,70.56 74.02,68.23 74.02,63.66 69.7,59.34 69.7,58.55 69.43,58.28 69.43,54.05 69.83,53.65 69.83,46.38 71.43,44.78 71.43,39.85 71.78,39.5 71.78,38.16 71.53,37.9 71.53,37.46 71.78,37.21 71.78,36.77 71.53,36.52 71.53,36.08 71.78,35.83 71.78,35.39 71.53,35.14 71.53,34.7 71.78,34.45 71.78,34.01 71.53,33.76 71.53,33.32 71.78,33.06 71.78,32.63 71.53,32.37 71.53,31.94 71.78,31.68 71.78,31.25 71.53,30.99 71.53,30.56 71.78,30.3 71.78,29.19 68.64,26.05 68.64,25.49 67.3,24.16 62.48,24.16 62.01,23.69 59.19,23.69 58.82,23.32 55.99,23.32 55.5,23.81 55.49,23.81 55.46,23.84 50.86,23.84 49.95,22.93 49.95,22.47 49.78,22.3 48.74,22.3 48.47,22.57 48.47,23.38 45.73,26.13 45.16,27.5 44.95,27.71 44.58,27.86 44.11,27.86 43.94,28.04 43.94,28.19 44.17,28.41 v1(44.31,28.41)
USB3_3_TYPEA2_HUB_TX2_N: length 132.6
  TOP w0.188: v1(38.53,28.41) 38.74,28.21 38.74,27.94 38.58,27.78 T10.4 38.58,26.71 R270.1 ; C376.2 93.72,70.84 v1(93.31,70.42)
  ART04 w0.173: v1(38.53,28.41) 38.8,28.14 38.8,27.25 39.59,26.46 44.47,26.46 55.05,15.88 61.87,15.88 62.87,14.88 74.25,14.88 75.08,15.72 75.08,16.62 74.27,17.43 74.27,21.39 73.96,21.7 73.96,27.09 72.01,31.81 72.01,40.76 70.25,44.99 70.02,45.22 69.19,47.24 69.19,50.84 69.95,52.68 69.95,62.15 71.4,63.6 71.4,66.27 71.57,66.44 71.78,66.44 71.96,66.27 v1(71.96,66.17)
  BOTTOM w0.188: v1(93.31,70.42) 93.02,70.71 92.33,70.71 91.92,71.12 91.92,71.85 91.19,72.59 85.35,72.59 84.54,73.39 83.03,74.02 81.2,74.02 80.11,72.92 80.11,66.32 77.8,64.01 73.2,64.01 72.57,64.64 72.57,66.25 72.38,66.44 72.23,66.44 v1(71.96,66.17)
USB3_3_TYPEA2_HUB_TX2_P: length 132.6
  TOP w0.188: v1(39.46,28.41) 39.24,28.2 39.24,27.93 39.39,27.78 T10.1 39.39,26.71 R271.1 ; v1(93.31,71.31) 92.84,70.84 C374.2
  ART04 w0.173: v1(71.96,67.1) 71.96,67 71.78,66.82 71.41,66.82 71.02,66.43 71.02,63.76 69.57,62.31 69.57,52.76 68.81,50.92 68.81,47.16 69.7,45 69.93,44.78 71.63,40.68 71.63,31.73 73.58,27.01 73.58,21.54 73.89,21.23 73.89,17.27 74.7,16.46 74.7,15.88 74.09,15.27 63.02,15.27 62.03,16.26 55.21,16.26 44.63,26.84 43,26.84 42.83,27.01 42.83,27.04 42.66,27.22 42.31,27.22 42.14,27.04 42.14,27.01 41.97,26.84 41.62,26.84 41.45,27.01 41.45,27.04 41.28,27.22 40.93,27.22 40.76,27.04 40.76,27.01 40.58,26.84 39.75,26.84 39.19,27.41 39.19,28.14 v1(39.46,28.41)
  BOTTOM w0.188: v1(71.96,67.1) 72.23,66.82 72.54,66.82 72.95,66.41 72.95,64.8 73.36,64.39 77.64,64.39 79.73,66.48 79.73,73.08 81.05,74.4 83.11,74.4 84.76,73.71 85.5,72.97 91.35,72.97 92.3,72.01 92.3,71.28 92.49,71.09 93.09,71.09 v1(93.31,71.31)
USB3_CON_RX1_N: length 1.2
  TOP w0.188: T3.4 106.04,12.41 106.43,12.8 U5.12
USB3_CON_RX1_P: length 1.2
  TOP w0.188: U5.13 106.93,12.59 106.54,12.2 T3.1
USB3_CON_RX2_N: length 1.2
  TOP w0.188: T4.4 108.85,12.08 108.43,12.5 U5.16
USB3_CON_RX2_P: length 1.2
  TOP w0.188: U5.17 108.93,12.61 109.35,12.19 T4.1
USB3_CON_TX1_N: length 1
  TOP w0.188: U5.14 107.43,12.02 T2.4
USB3_CON_TX1_P: length 1
  TOP w0.188: U5.15 107.93,12.01 T2.1
USB3_CON_TX2_N: length 1.8
  TOP w0.188: U5.18 109.43,12.65 109.91,12.17 110.4,12.17 T1.4
USB3_CON_TX2_P: length 1.8
  TOP w0.188: U5.19 109.93,12.74 110.12,12.55 110.72,12.55 110.92,12.34 T1.1
USB3_SSRX1_N: length 15.5
  TOP w0.188: T3.3 105.98,11.37 D4.5 D4.6 105.98,9.15 v1(105.46,8.63)
  ART04 w0.102: 102.59,7.26 102.57,7.26 102.49,7.19 102.23,7.19 101.74,7.68 101.74,7.79 101.72,7.81
  ART04 w0.173: 101.72,7.81 101.62,7.91 101.62,9.49 102.52,10.39 104.32,10.39 104.51,10.2 104.51,9.95 104.29,9.73 104.29,9.48 104.53,9.24 104.77,9.24 105,9.47 105.25,9.47 105.64,9.07 105.64,8.8 v1(105.46,8.63) ; 102.59,7.26 102.88,7.26 103.45,6.69 103.45,5.15 J4.22
USB3_SSRX1_P: length 15.5
  TOP w0.188: v1(106.22,8.63) 106.48,8.89 D4.7 D4.4 106.48,11.37 T3.2
  ART04 w0.102: 102.59,6.88 102.57,6.88 102.49,6.96 102.14,6.96 101.58,7.52 101.47,7.52 101.45,7.54
  ART04 w0.173: v1(106.22,8.63) 106.02,8.83 106.02,9.23 104.48,10.77 102.36,10.77 101.24,9.65 101.24,7.75 101.45,7.54 ; J4.23 103.07,4.99 103.07,6.53 102.72,6.88 102.59,6.88
USB3_SSRX2_N: length 5.8
  TOP w0.188: T4.3 108.85,10.91 109.17,10.59 D6.5 D6.6 109.17,8.49 108.73,8.05 108.13,8.05 107.72,7.64 107.72,7.41 107.6,7.29 J4.10
USB3_SSRX2_P: length 5.8
  TOP w0.188: J4.11 108.1,7.48 108.28,7.67 108.89,7.67 109.63,8.41 109.63,8.94 109.67,8.98 D6.7 D6.4 109.67,10.73 109.35,11.04 T4.2
USB3_SSTX1_N: length 12.8
  TOP w0.188: v1(104.14,7.72) 104.02,7.6 104.02,7.33 104.1,7.26 J4.3 ; v1(107.75,8.63) 107.48,8.89 D4.9 D4.2 107.48,10.76 107.44,10.8 T2.3
  ART03 w0.173: v1(107.75,8.63) 107.88,8.63 108.51,8 108.51,7.9 108.36,7.75 108.08,7.75 107.92,7.6 107.92,7.38 108.08,7.23 108.36,7.23 108.51,7.08 108.51,6.93 108.34,6.76 107.3,6.76 106.89,7.16 103.83,7.16 103.66,7.34 103.66,7.59 103.78,7.72 v1(104.14,7.72)
USB3_SSTX1_P: length 12.7
  TOP w0.188: v1(108.51,8.63) 108.14,9 D4.10 D4.1 107.98,10.76 107.94,10.8 T2.2 ; v1(103.22,7.72) 103.22,7.7 103.42,7.5 103.6,7.08 J4.2
  ART03 w0.173: v1(103.22,7.72) 103.22,7.2 103.63,6.78 106.73,6.78 107.14,6.38 108.49,6.38 108.89,6.77 108.89,8.16 108.51,8.54 v1(108.51,8.63)
USB3_SSTX2_N: length 8.9
  TOP w0.188: v1(110.46,8.6) 110.67,8.81 D6.9 D6.2 110.67,11.05 110.57,11.15 T1.3
  ART04 w0.173: J4.15 108.18,5.09 108.18,6.17 108.01,6.35 107.92,6.35 107.75,6.52 107.75,6.86 107.92,7.04 108.01,7.04 108.18,7.21 108.18,7.47 109.09,8.38 110.24,8.38 v1(110.46,8.6)
USB3_SSTX2_P: length 8.9
  TOP w0.188: v1(111.38,8.6) 111.17,8.81 D6.10 D6.1 111.17,11.31 T1.2
  ART04 w0.173: v1(111.38,8.6) 110.78,8 109.25,8 108.56,7.31 108.56,5.05 J4.14
USB3_SW_SEL: length 25.1
  TOP w0.203: U5.9 106.43,15.9 105.56,16.76 R243.1 105.01,16.76 104.39,17.37 104.39,18.92 103.63,19.68 103.63,21.29 102.21,22.71 v1(102.21,23.02)
  TOP w0.254: R259.2 98.3,35.69 v1(98.55,35.94)
  ART03 w0.203: v1(98.55,35.94) 98.55,26.56 102.09,23.02 v1(102.21,23.02)
USB20_TYPEA1_HUB0_DN: length 35.2
  TOP w0.188: U38.8 94.58,97.37 95.02,96.93 95.02,96.83 v1(95.53,96.32) ; v1(85.4,76.73) 85.62,76.51 R539.1
  ART03 w0.173: v1(85.4,76.73) 85.4,76.79 86.3,77.7 89.76,77.7 93.5,81.43 93.5,81.87 98.41,86.78 98.41,90.49 99.18,91.25 99.18,94.58 97.97,95.78 95.51,95.78 95.41,95.88 95.41,96.2 v1(95.53,96.32)
USB20_TYPEA1_HUB0_DP: length 35.3
  TOP w0.188: v1(85.4,77.62) 85.62,77.84 R477.1 ; v1(94.64,96.32) 94.64,96.77 94.42,96.99 93.15,96.99 93.14,96.97 U38.7
  ART03 w0.173: v1(85.4,77.62) 85.65,77.62 86.11,78.08 89.61,78.08 93.12,81.59 93.12,82.02 94.73,83.64 94.73,83.91 95.08,84.26 95.35,84.26 95.71,84.62 95.71,84.89 96.06,85.24 96.33,85.24 98.03,86.94 98.03,90.65 98.8,91.41 98.8,91.76 98.5,92.05 98.5,92.45 98.8,92.74 98.8,93.14 98.5,93.43 98.5,93.83 98.8,94.13 98.8,94.42 98.7,94.52 98.45,94.52 98.26,94.34 98.02,94.34 97.77,94.58 97.77,94.82 97.96,95.01 97.96,95.26 97.82,95.4 95.35,95.4 95.03,95.72 95.03,95.93 v1(94.64,96.32)
USB20_TYPEA1_HUB1_DN: length 3.3
  TOP w0.188: R538.1 89.02,76.75 89.31,77.03 89.31,77.22 90.31,78.22 U36.72
USB20_TYPEA1_HUB1_DP: length 3.3
  TOP w0.188: U36.71 90.17,78.62 90.08,78.53 89.61,78.53 89.31,78.24 89.31,77.76 89.17,77.62 88.66,77.62 R476.1
USB20_TYPEA1_HUB_DN: length 86.2
  TOP w0.188: v1(87.16,77.17) 87.63,76.7 R538.2 ; v1(54.01,25.27) 53.7,25.59 53.7,25.65 53.23,26.12 52.65,26.37 T5.4 51.51,26.37 R260.1
  ART03 w0.173: v1(54.01,25.27) 54.01,25 54.18,24.83 58.58,24.83 58.89,25.14 62.24,25.14 62.42,25.32 65.45,25.32 66.65,26.52 66.65,27.67 69.47,30.49 69.47,40.63 67.74,42.36 67.74,44.06 66.93,44.88 66.93,53.39 65.3,55.01 65.3,59.39 66.98,61.06 67.05,61.09 70.35,62.45 72.52,64.62 72.52,68.36 77.72,73.56 78.36,73.56 78.53,73.73 78.53,73.82 78.7,73.99 79.05,73.99 79.22,73.82 79.22,73.73 79.39,73.56 79.74,73.56 79.91,73.73 79.91,73.82 80.08,73.99 80.43,73.99 80.6,73.82 80.6,73.73 80.77,73.56 81.12,73.56 81.45,73.89 81.83,73.89 82.16,73.56 84.28,73.56 87.38,76.66 87.38,76.96 v1(87.16,77.17)
USB20_TYPEA1_HUB_DP: length 85.9
  TOP w0.188: v1(53.09,25.27) 53.23,25.42 53.23,25.58 53.08,25.73 52.75,25.73 52.58,25.55 T5.1 51.51,25.55 R261.1 ; R477.2 87.63,77.59 v1(88.05,77.17)
  ART03 w0.173: v1(53.09,25.27) 53.64,24.71 53.76,24.71 54.03,24.45 58.74,24.45 59.04,24.75 62.39,24.75 62.58,24.94 65.61,24.94 67.03,26.37 67.03,27.51 69.85,30.33 69.85,40.79 68.12,42.52 68.12,44.22 67.31,45.04 67.31,53.55 65.68,55.17 65.68,59.23 67.19,60.73 70.56,62.13 72.9,64.47 72.9,68.2 77.88,73.18 84.44,73.18 87.76,76.5 87.76,76.88 v1(88.05,77.17)
USB20_TYPEA2_HUB0_DN: length 45.9
  TOP w0.188: v1(91.21,68.61) 91.44,68.83 R543.1 ; v1(92.65,92.08) 92.56,91.98 92.31,91.98 92.13,92.17 92.13,92.7 91.49,93.34 U38.75
  BOTTOM w0.188: v1(92.65,92.08) 92.86,91.86 94.57,91.86 98.01,90.44 98.88,89.57 98.88,87.16 100.01,86.04 101.54,86.04 103.63,83.95 103.63,77.98 102.34,76.68 102.34,72.18 102.11,71.96 102.11,71.58 101.77,71.24 101.39,71.24 99.94,69.79 99.94,69.34 99.64,69.03 99.19,69.03 98.88,68.72 98.88,68.27 98.57,67.97 98.12,67.97 97.82,67.67 92.58,67.67 91.63,68.61 v1(91.21,68.61)
USB20_TYPEA2_HUB0_DP: length 45.9
  TOP w0.188: v1(92.65,91.19) 92.35,91.49 92.16,91.49 91.74,91.9 91.74,92.55 91.09,93.2 U38.74 ; v1(90.33,68.61) 90.1,68.83 R541.1
  BOTTOM w0.188: v1(90.33,68.61) 90.55,68.61 91.03,69.09 91.69,69.09 92.73,68.05 97.66,68.05 101.96,72.34 101.96,76.84 103.25,78.14 103.25,83.79 101.38,85.66 99.85,85.66 98.5,87.01 98.5,89.41 97.79,90.12 94.49,91.48 92.95,91.48 v1(92.65,91.19)
USB20_TYPEA2_HUB1_DN: length 6
  TOP w0.188: U36.6 93.75,74.7 93.85,74.6 93.85,74.07 93.41,73.63 93.34,73.44 92.35,72.45 92.08,72.45 91.89,72.64 91.59,72.64 91.26,72.31 91.26,71.83 R542.1
USB20_TYPEA2_HUB1_DP: length 6.1
  TOP w0.188: U36.5 93.35,74.47 93.01,73.66 92.38,73.03 91.51,73.03 90.88,72.76 90.33,72.21 90.1,71.66 R540.1
USB20_TYPEA2_HUB_DN: length 86.3
  TOP w0.188: R266.1 51.51,24.33 T8.4 52.37,24.33 52.58,24.12 53.26,24.12 v1(54.39,22.99) ; v1(90.78,71.26) 91.19,70.84 R543.2
  ART03 w0.173: v1(54.39,22.99) 54.39,22.99 54.18,22.78 54.18,22.53 55.07,21.64 59.35,21.64 60.22,22.5 67.59,22.5 69.9,24.82 69.9,25.53 70.64,26.26 72.46,26.26 73.41,27.21 73.41,40.63 72.81,41.23 72.81,52.96 72.54,53.23 72.54,59.16 75.51,62.13 75.51,68.1 76.52,69.11 78.15,69.11 79.45,70.41 88.54,70.41 89.14,71.01 90.52,71.01 v1(90.78,71.26)
USB20_TYPEA2_HUB_DP: length 86.4
  TOP w0.188: R267.1 51.51,23.52 T8.1 52.35,23.52 52.57,23.74 53.1,23.74 53.47,23.37 v1(53.47,22.99) ; v1(90.78,70.37) 90.31,70.84 R541.2
  ART03 w0.173: v1(90.78,70.37) 90.52,70.62 89.29,70.62 88.7,70.03 79.6,70.03 78.31,68.73 76.68,68.73 75.89,67.94 75.89,61.97 72.92,59 72.92,53.38 73.19,53.12 73.19,41.39 73.79,40.79 73.79,27.05 72.62,25.88 70.8,25.88 70.28,25.37 70.28,24.66 67.75,22.12 60.38,22.12 59.51,21.26 57.95,21.26 57.67,20.98 57.26,20.98 56.98,21.26 54.91,21.26 53.7,22.48 53.7,22.76 v1(53.47,22.99)
USB30_PWR0_EN1: length 119.3
  TOP w0.203: v1(76.07,95.43) 76.07,96.22 R549.2 ; U8.4 v1(47.96,33.31) 48,33.27 R274.2 ; U38.26 v1(89.49,101.83)
  ART03 w0.203: v1(47.96,33.31) 48.87,33.31 51.89,36.34 51.89,39.95 v1(53.09,41.15) ; v1(76.07,95.43) 76.4,95.1 76.4,87.89 80.78,83.51 80.78,79.69 79.51,78.42 77.2,78.42 76.66,77.88 69.39,77.88 60.93,69.42 60.93,58.76 58.46,56.29 55.93,56.29 54.2,54.56 54.2,52.47 54.69,51.98 v1(54.69,51.92)
  ART04 w0.203: v1(89.49,101.83) 89.49,103.74 86.91,106.32 86.13,106.32 85.12,107.34 81.08,107.34 75.82,102.08 75.82,96.39 76.07,96.14 v1(76.07,95.43) ; v1(53.09,41.15) 53.09,41.4 51.77,42.72 51.77,44.43 52.83,45.49 55.45,45.49 56.74,46.79 56.74,47.56 54.23,50.07 54.23,51.46 v1(54.69,51.92)
USB30_PWR0_EN2: length 174.7
  TOP w0.203: U38.19 93.34,101.77 93.55,101.97 v1(93.55,102.48) ; R277.2 59.61,18.76 v1(59.32,18.76) U9.4 ; R555.2 v1(105.26,89.26)
  ART03 w0.203: v1(45.09,38.1) 44.76,37.78 44.76,34.55 40.18,29.97 40.18,28.48 40.38,28.28 40.38,25.37 40.79,24.96 44.5,24.96 48.04,21.42 50.61,21.42 53.28,18.76 v1(59.32,18.76) ; v1(57.02,40.51) 56.57,40.97 56.57,45 55.78,45.79 55.78,48.72 54.1,50.39 54.1,51.99 53.8,52.3 53.8,54.73 55.76,56.69 58.29,56.69 60.53,58.93 60.53,70.15 63.86,73.47 63.86,83.36 v1(65.06,84.57) ; v1(93.55,102.48) 94.39,103.33 100.6,103.33 102.31,101.61 102.31,101.5 105.77,98.04 105.77,91.9 105.26,91.39 v1(105.26,89.26)
  ART04 w0.203: v1(65.06,84.57) 66.4,85.9 72.89,85.9 73.68,86.7 75,88.01 79.86,88.01 80.44,88.6 87.15,88.6 87.6,89.05 87.6,89.53 88.11,90.04 90.83,90.04 91.08,90.3 93.71,90.3 95.09,88.93 98.81,88.93 100,90.12 104.39,90.12 v1(105.26,89.26)
  BOTTOM w0.203: v1(57.02,40.51) 56.26,41.27 56.26,41.77 55.84,42.19 53.46,42.19 52.01,40.74 49.6,40.74 48.38,39.52 47.78,39.52 47.04,38.79 45.77,38.79 v1(45.09,38.1)
USB30_PWR1_EN1: length 50.4
  TOP w0.203: R550.1 103.19,85.28 103.53,84.94 104.09,84.94 104.34,85.19 104.34,95.1 v1(103.94,95.5) ; R547.1 73.79,93.37 Q1.1 74.81,92.3 C311.2 R548.2 v1(74.9,90.45)
  ART04 w0.203: v1(74.9,90.45) 74.9,89.43 75.92,88.42 78.75,88.42 79.82,89.48 85.18,89.48 88.55,92.86 88.55,93.18 89.35,93.98 91.59,93.98 91.82,94.21 91.82,94.21 91.9,94.28 97.63,94.28 98.82,95.48 103.91,95.48 v1(103.94,95.5)
USB30_PWR1_EN2: length 4.4
  TOP w0.203: Q6.1 107.42,85.83 107.04,85.45 R554.2 C313.2 R458.1 R551.1
USB_12M_X0_HUB1: length 42
  TOP w0.203: U36.75 91.49,77.02 v1(91.73,76.78) ; R558.1 v1(65.43,90.78)
  ART03 w0.203: v1(76.45,81.28) 76.81,81.64 76.81,84.06 73.47,87.4 69.53,87.4 68.86,88.07 68.86,89.43 67.97,90.32 65.89,90.32 v1(65.43,90.78)
  ART04 w0.203: v1(76.45,81.28) 76.91,80.82 76.91,78.64 79.83,75.72 82.59,75.72 84.37,73.94 85.99,73.94 86.46,73.47 86.46,73.05 86.92,72.59 87.96,72.59 90.91,75.54 90.91,76.14 91.55,76.78 v1(91.73,76.78)
USB_12M_XI_HUB1: length 40.8
  TOP w0.203: R559.1 v1(66.45,90.78) ; U36.74 91.61,77.42 v1(91.73,77.54)
  ART03 w0.203: v1(77.6,81.28) 77.22,81.66 77.22,84.23 73.63,87.81 69.7,87.81 69.27,88.24 69.27,89.6 68.14,90.73 66.5,90.73 v1(66.45,90.78)
  ART04 w0.203: v1(77.6,81.28) 77.32,81 77.32,78.81 80,76.12 82.76,76.12 84.54,74.35 86.16,74.35 86.87,73.64 86.87,73.22 87.08,73 87.79,73 90.5,75.71 90.5,76.31 v1(91.73,77.54)
USB_25M_XI_HUB1: length 3.9
  TOP w0.203: R579.1 80.9,93.79 81.19,94.08 81.95,94.08 83.24,95.37 U38.55
USB_25M_XO_HUB1: length 2.7
  TOP w0.203: R580.1 81.94,93.57 83.34,94.97 U38.56
USB_TYPEC_CON_DN: length 14.4
  TOP w0.188: v1(106.45,7.64) 106.45,7.62 106.1,7.26 J4.7 ; T21.2 103.71,12.52 103.48,12.29 103.48,9.68 v1(103.43,9.62) 103.76,9.29 U6.1
  ART04 w0.173: J4.19 105.66,5.97 105.66,6.53 106.06,6.93 106.28,6.93 106.45,7.11 v1(106.45,7.64)
  BOTTOM w0.102: v1(103.43,9.62) 103.43,9.3 103.56,9.17 104.03,9.17 104.13,9.27 104.13,9.88 104.23,9.98 104.44,9.98 104.54,9.88 104.54,9.27 104.64,9.17 104.79,9.17 104.95,9.01 104.95,8.5 105.3,8.15 106.35,8.15 106.45,8.05 v1(106.45,7.64)
USB_TYPEC_CON_DP: length 13.8
  TOP w0.188: J4.6 105.6,7.55 v1(105.69,7.64) ; 102.84,9.29 v1(103.43,8.7) ; 102.84,9.29 102.97,9.42 102.97,9.91 103.1,10.04 103.1,12.32 102.9,12.52 T21.3 ; 102.84,9.29 U6.6
  ART04 w0.102: 106.05,8.08 106.63,8.08 106.86,7.85 106.86,7.47
  ART04 w0.173: 106.86,7.47 106.86,6.98 106.44,6.55 106.21,6.55 106.04,6.38 106.04,5.97 J4.18 ; 106.05,8.08 105.69,7.72 v1(105.69,7.64)
  BOTTOM w0.102: v1(103.43,8.7) 104.02,8.94 104.52,8.94 104.72,8.74 104.72,8.41 105.49,7.64 v1(105.69,7.64)
USB_VBUS: length 78.9
  TOP w0.203: R244.2 101.01,12.52 v1(101.32,12.83) ; v1(74.27,39.96) 74.18,39.88 72.94,39.88 71.22,38.16 v1(70.76,38.16) ; J16.115 69,55.03 67.89,53.92 v1(67.89,53.37)
  ART03 w0.203: v1(67.89,53.37) 69.39,51.87 69.39,45.7 70.44,44.65 70.44,38.48 v1(70.76,38.16)
  ART04 w0.203: v1(101.32,12.83) 101.32,12.37 100.11,11.16 96.8,11.16 96.46,11.51 78.71,11.51 77.8,12.42 77.8,21.59 76.15,23.24 76.15,30.53 74.17,32.51 74.17,35.89 74.27,35.99 v1(74.27,39.96)
USB_VBUS_CON: length 18.2
  TOP w0.254: R14.2 101.68,26.72 101.4,27 101.4,29.84 101.14,30.1 97.18,30.1 96.83,29.74 U7.8 96.83,27.26 95.96,26.39 v1(95.96,22.71) C119.1 ; R247.2 101.52,21.06 v1(102.21,21.75)
  vias: v1(97.64,11.74) v1(98.15,12.25)
V_3V3_HUB: length 26.3
  TOP w0.381: R640.2 v1(19.53,112.04) C318.1 19.06,113.25 U37.8 17.91,114.4 16.36,115.95 R619.1 ; v1(31.62,116.2) R630.2 31.01,116.96 30.2,117.77 R642.2 R607.1
  ART03 w0.381: v1(31.62,116.2) 31.06,116.2 29.68,117.58 25.07,117.58 v1(19.53,112.04)
